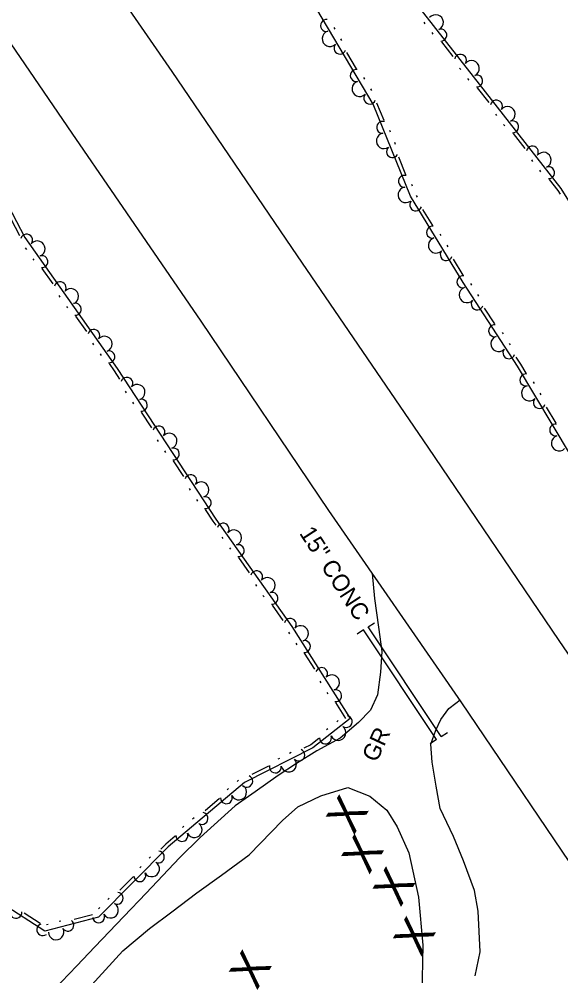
# Model space of a CAD drawing. Extents: x 2030130 to 2036320, y 723205 to 762423.
# Drawn here: x 2034186.4 to 2034304.6, y 759843.4 to 760052.2 of the extents above; entities that cross this region are included whole.
import ezdxf

# ---------------------------------------------------------------- set-up
doc = ezdxf.new("R2010")
doc.units = 0
for name, color, linetype in [('Draft_Station Labels Major', 7, 'Continuous'), ('Draft_Station Tics Major', 7, 'Continuous'), ('Draft_Station Tics Minor', 7, 'Continuous'), ('Old_Level_23', 7, 'Continuous'), ('Old_Level_26', 7, 'Continuous')]:
    doc.layers.add(name, color=color, linetype=linetype)

msp = doc.modelspace()

# ---------------------------------------------------------------- linework, layer by layer
at = {"layer": 'Draft_Station Labels Major'}
for points in [[(2033718.38, 760730.67), (2033746.51, 760689.6), (2033774.62, 760648.49), (2033802.7, 760607.26), (2033830.67, 760566.06), (2033858.89, 760525.01), (2033886.8, 760483.79), (2033914.88, 760442.66), (2033945.45, 760397.69), (2033973.64, 760356.6), (2034001.68, 760315.42), (2034029.6, 760274.28), (2034057.68, 760233.24), (2034085.75, 760192.04), (2034113.77, 760150.87), (2034141.95, 760109.94), (2034159.83, 760083.11), (2034175.33, 760060.45), (2034197.95, 760027.35), (2034226.1, 759986.31), (2034253.95, 759945.01), (2034282.77, 759903.21), (2034311.52, 759860.74)], [(2034332.4, 759875.51), (2034304.28, 759916.6), (2034275.65, 759958.8), (2034247.14, 760000.6), (2034219.84, 760040.78), (2034191.61, 760081.68), (2034163.74, 760123.03), (2034135.88, 760163.98), (2034107.11, 760206.11), (2034080.34, 760245.23), (2034051.49, 760287.62), (2034022.91, 760329.48), (2033995.09, 760369.99), (2033966.89, 760411.11), (2033935.74, 760457.29), (2033907.97, 760498.26), (2033880.46, 760539.38), (2033851.33, 760582.23)], [(2034263.43, 759931.23), (2034263.96, 759925.76), (2034264.85, 759919.56), (2034265.6, 759914.2), (2034265.3, 759909.74), (2034264.64, 759904.78), (2034263.09, 759901.44), (2034260.51, 759898.71), (2034256.46, 759895.31), (2034251.41, 759892.53), (2034246.96, 759889.75), (2034242.98, 759887.18), (2034237.9, 759883.6), (2034233.6, 759880.5), (2034225.96, 759873.65), (2034221.39, 759869.16), (2034214.15, 759861.5), (2034209.26, 759856.38), (2034202.93, 759849.74), (2034199.01, 759845.6), (2034193.99, 759840.41)], [(2034285.94, 759843.41), (2034287.05, 759848.7), (2034286.58, 759857.57), (2034285.78, 759862.06), (2034283.38, 759868.54), (2034281.18, 759873.85), (2034278.31, 759879.94), (2034277.4, 759884.81), (2034276.56, 759890.09), (2034276.23, 759893.99), (2034277.35, 759897.08), (2034278.42, 759899.37), (2034280.2, 759901.79), (2034281.69, 759902.96), (2034282.66, 759903.64)], [(2034201.48, 759840.6), (2034209.03, 759848.89), (2034214.9, 759853.77), (2034219.75, 759857.37), (2034225.21, 759861.55), (2034230.58, 759865.43), (2034236.63, 759869.86), (2034243.9, 759877.35), (2034247.25, 759880.33), (2034252.29, 759882.71), (2034258.18, 759884.52), (2034262.96, 759882.65), (2034266.63, 759879.62), (2034268.94, 759875.92), (2034271.46, 759870.27), (2034273.55, 759860.57), (2034274.52, 759850.16), (2034274.27, 759839.19)]]:
    msp.add_lwpolyline(points, dxfattribs=at)
msp.add_spline([(2034040.65, 759871.53), (2034053.57, 759856.73), (2034085.12, 759821.41), (2034121.23, 759781.88), (2034160.8, 759738.89), (2034194.89, 759702.59)], degree=3, dxfattribs=at)
at = {"layer": 'Draft_Station Tics Major'}
for points in [[(2033865.22, 760655.09), (2033891.74, 760610.39), (2033928.27, 760560.61), (2033957.26, 760512.4), (2033990.84, 760466.46), (2034027.29, 760415.57), (2034062.79, 760367.8), (2034100.45, 760308.07), (2034126.3, 760269.13), (2034147.67, 760241.66), (2034171.15, 760213.5), (2034188.43, 760192.75), (2034201.98, 760164.61), (2034214.77, 760146.29), (2034228.35, 760126.12), (2034239.08, 760107.39), (2034248.43, 760090.51), (2034260.06, 760075.4), (2034270.93, 760058.37), (2034285.47, 760039.75), (2034304.65, 760015.27), (2034321.95, 759987.59), (2034348.43, 759946.8)], [(2034326.75, 759923.45), (2034306.73, 759957.16), (2034295.18, 759976.5), (2034283.32, 759994.79), (2034271.8, 760013.59), (2034263.7, 760033.69), (2034251.35, 760054.43), (2034226.75, 760080.43), (2034216.04, 760102), (2034205.31, 760120.49), (2034188.73, 760144.18), (2034176.71, 760159.19)], [(2034255.38, 760050.07), (2034255.17, 760050.42)], [(2034274.7, 760051.55), (2034274.95, 760051.23)], [(2034276.46, 760049.29), (2034276.71, 760048.97)], [(2034256.84, 760047.6), (2034256.63, 760047.96)], [(2034278.55, 760047.28), (2034281.07, 760044.05)], [(2034260.06, 760041.4), (2034257.96, 760044.93)], [(2034282.52, 760041.53), (2034282.77, 760041.21)], [(2034261.88, 760039.15), (2034261.67, 760039.5)], [(2034284.28, 760039.27), (2034284.5, 760038.99), (2034284.53, 760038.95)], [(2034263.35, 760036.68), (2034263.14, 760037.03)], [(2034286.38, 760037.26), (2034288.91, 760034.03)], [(2034266.04, 760030.08), (2034264.51, 760033.88)], [(2034290.35, 760031.52), (2034290.61, 760031.2)], [(2034173.85, 760031), (2034187.64, 760004.61), (2034207.84, 759975.95), (2034229.38, 759943.13), (2034245.9, 759919.69), (2034258.64, 759899.6), (2034250.52, 759893.18), (2034235.61, 759885.65), (2034218.97, 759871.56), (2034203.75, 759856.25), (2034192.07, 759853.18), (2034182.82, 759859.15)], [(2034292.12, 760029.26), (2034292.38, 760028.94)], [(2034267.49, 760027.57), (2034267.34, 760027.95)], [(2034294.22, 760027.25), (2034296.75, 760024.02)], [(2034268.56, 760024.91), (2034268.41, 760025.29)], [(2034270.79, 760018.29), (2034269.26, 760022.09)], [(2034298.2, 760021.51), (2034298.45, 760021.19)], [(2034299.97, 760019.25), (2034300.22, 760018.93)], [(2034302.06, 760017.24), (2034303.98, 760014.8), (2034304.46, 760014.03)], [(2034272.24, 760015.78), (2034272.09, 760016.16)], [(2034273.37, 760013.37), (2034273.16, 760013.72)], [(2034276.67, 760007.21), (2034274.52, 760010.71)], [(2034184.6, 760008.66), (2034186.5, 760005.02)], [(2034278.52, 760004.98), (2034278.3, 760005.33)], [(2034187.77, 760002.29), (2034188.01, 760001.95)], [(2034280.02, 760002.53), (2034279.8, 760002.88)], [(2034189.43, 759999.94), (2034189.66, 759999.6)], [(2034283.31, 759996.37), (2034281.17, 759999.87)], [(2034191.41, 759997.83), (2034193.78, 759994.48)], [(2034285.18, 759994.19), (2034284.95, 759994.53)], [(2034195.1, 759991.89), (2034195.33, 759991.56)], [(2034286.74, 759991.78), (2034286.51, 759992.12)], [(2034196.75, 759989.55), (2034196.99, 759989.21)], [(2034198.74, 759987.44), (2034201.1, 759984.09)], [(2034290.19, 759985.71), (2034287.96, 759989.15)], [(2034292.09, 759983.53), (2034291.87, 759983.87)], [(2034202.42, 759981.5), (2034202.66, 759981.17)], [(2034293.66, 759981.12), (2034293.43, 759981.46)], [(2034204.08, 759979.16), (2034204.31, 759978.82)], [(2034206.07, 759977.05), (2034207.16, 759975.49), (2034208.35, 759973.68)], [(2034297.05, 759974.97), (2034295.88, 759976.94), (2034294.88, 759978.49)], [(2034298.88, 759972.72), (2034298.67, 759973.07)], [(2034209.58, 759971.05), (2034209.81, 759970.71)], [(2034211.16, 759968.65), (2034211.39, 759968.31)], [(2034300.35, 759970.25), (2034300.14, 759970.61)], [(2034303.57, 759964.06), (2034301.47, 759967.58)], [(2034213.08, 759966.48), (2034215.33, 759963.05)], [(2034216.56, 759960.43), (2034216.79, 759960.08)], [(2034218.14, 759958.02), (2034218.36, 759957.68)], [(2034220.06, 759955.85), (2034222.31, 759952.42)], [(2034223.54, 759949.8), (2034223.76, 759949.45)], [(2034225.11, 759947.4), (2034225.34, 759947.05)], [(2034227.03, 759945.22), (2034228.71, 759942.67), (2034229.33, 759941.79)], [(2034230.65, 759939.21), (2034230.88, 759938.87)], [(2034232.3, 759936.86), (2034232.53, 759936.53)], [(2034234.29, 759934.75), (2034236.65, 759931.4)], [(2034237.97, 759928.81), (2034238.2, 759928.48)], [(2034239.62, 759926.47), (2034239.86, 759926.13)], [(2034241.61, 759924.36), (2034243.97, 759921)], [(2034245.23, 759918.45), (2034245.45, 759918.11)], [(2034246.77, 759916.03), (2034246.99, 759915.68)], [(2034248.65, 759913.82), (2034250.85, 759910.36)], [(2034252.04, 759907.72), (2034252.26, 759907.37)], [(2034253.57, 759905.29), (2034253.79, 759904.95)], [(2034255.46, 759903.09), (2034257.66, 759899.62)], [(2034256.06, 759899.13), (2034255.74, 759898.87)], [(2034253.81, 759897.35), (2034253.49, 759897.09)], [(2034251.81, 759895.24), (2034250.07, 759893.87), (2034248.54, 759893.09)], [(2034245.79, 759892.17), (2034245.42, 759891.98)], [(2034243.23, 759890.87), (2034242.86, 759890.69)], [(2034240.85, 759889.21), (2034237.19, 759887.36)], [(2034234.29, 759886.14), (2034233.98, 759885.87)], [(2034232.1, 759884.29), (2034231.79, 759884.02)], [(2034230.17, 759882.12), (2034227.04, 759879.47)], [(2034224.59, 759877.93), (2034224.27, 759877.66)], [(2034222.4, 759876.07), (2034222.08, 759875.81)], [(2034220.47, 759873.9), (2034218.41, 759872.16), (2034217.37, 759871.11)], [(2034215.06, 759869.37), (2034214.77, 759869.08)], [(2034213.03, 759867.33), (2034212.74, 759867.04)], [(2034211.3, 759865.01), (2034208.41, 759862.1)], [(2034206.1, 759860.35), (2034205.81, 759860.06)], [(2034204.07, 759858.32), (2034203.78, 759858.03)], [(2034190.99, 759854.85), (2034187.54, 759857.08)], [(2034202.4, 759856.74), (2034198.43, 759855.7)], [(2034192.78, 759854.64), (2034192.38, 759854.54)], [(2034195.55, 759855.37), (2034195.16, 759855.27)]]:
    msp.add_lwpolyline(points, dxfattribs=at)
for centre, radius, start, end in [((2034277.32, 760051.52), 1.69, 293.9308, 142.0033), ((2034253.48, 760050.85), 1.3, 81.5456, 282.3422), ((2034254.24, 760047.96), 1.69, 106.7409, 314.8133), ((2034278.44, 760048.75), 1.3, 268.7356, 109.5321), ((2034256.42, 760045.92), 1.3, 139.2121, 340.0086), ((2034282.73, 760043.26), 1.3, 326.402, 167.1986), ((2034285.14, 760041.5), 1.69, 293.9308, 142.0033), ((2034259.98, 760039.93), 1.3, 81.5456, 282.3422), ((2034286.26, 760038.73), 1.3, 268.8534, 109.65), ((2034260.75, 760037.04), 1.69, 106.7409, 314.8133), ((2034262.92, 760034.99), 1.3, 139.2121, 340.0086), ((2034290.56, 760033.24), 1.3, 326.5199, 167.3164), ((2034292.98, 760031.49), 1.69, 294.0487, 142.1212), ((2034265.74, 760028.63), 1.3, 72.7157, 273.5122), ((2034294.11, 760028.73), 1.3, 268.8534, 109.65), ((2034266.05, 760025.66), 1.69, 97.9109, 305.9834), ((2034267.88, 760023.31), 1.3, 130.3821, 331.1787), ((2034298.41, 760023.24), 1.3, 326.5199, 167.3164), ((2034300.82, 760021.48), 1.69, 294.0487, 142.1212), ((2034301.95, 760018.72), 1.3, 268.8534, 109.65), ((2034270.49, 760016.84), 1.3, 72.7157, 273.5122), ((2034270.8, 760013.87), 1.69, 97.9109, 305.9834), ((2034272.97, 760011.68), 1.3, 139.9358, 340.7323), ((2034276.61, 760005.74), 1.3, 82.2693, 283.0659), ((2034188.07, 760004), 1.3, 323.6174, 164.4139), ((2034277.41, 760002.86), 1.69, 107.4646, 315.5371), ((2034190.39, 760002.13), 1.69, 291.1462, 139.2187), ((2034191.38, 759999.31), 1.3, 265.9509, 106.7475), ((2034279.61, 760000.84), 1.3, 139.9358, 340.7323), ((2034283.25, 759994.9), 1.3, 82.2693, 283.0659), ((2034195.39, 759993.61), 1.3, 323.6174, 164.4139), ((2034197.72, 759991.73), 1.69, 291.1462, 139.2187), ((2034284.12, 759992.04), 1.69, 108.9411, 317.0136), ((2034198.7, 759988.92), 1.3, 265.9509, 106.7475), ((2034286.37, 759990.08), 1.3, 141.4123, 342.2088), ((2034290.17, 759984.23), 1.3, 83.7458, 284.5424), ((2034202.72, 759983.22), 1.3, 323.6174, 164.4139), ((2034205.04, 759981.34), 1.69, 291.1462, 139.2187), ((2034291.04, 759981.38), 1.69, 108.9411, 317.0136), ((2034206.03, 759978.53), 1.3, 265.9509, 106.7475), ((2034293.29, 759979.41), 1.3, 141.4123, 342.2088), ((2034209.94, 759972.76), 1.3, 321.7177, 162.5142), ((2034296.98, 759973.5), 1.3, 81.5934, 282.39), ((2034212.2, 759970.81), 1.69, 289.2465, 137.319), ((2034297.74, 759970.61), 1.69, 106.7887, 314.8612), ((2034213.09, 759967.96), 1.3, 264.0512, 104.8478), ((2034299.92, 759968.57), 1.3, 139.2599, 340.0564), ((2034216.92, 759962.13), 1.3, 321.7177, 162.5142), ((2034303.49, 759962.58), 1.3, 81.5934, 282.39), ((2034219.18, 759960.18), 1.69, 289.2465, 137.319), ((2034304.26, 759959.69), 1.69, 106.7887, 314.8612), ((2034220.07, 759957.33), 1.3, 264.0512, 104.8478), ((2034223.89, 759951.5), 1.3, 321.7177, 162.5142), ((2034226.15, 759949.55), 1.69, 289.2465, 137.319), ((2034227.04, 759946.7), 1.3, 264.0512, 104.8478), ((2034230.94, 759940.92), 1.3, 323.5986, 164.3952), ((2034233.27, 759939.05), 1.69, 291.1274, 139.1999), ((2034234.25, 759936.23), 1.3, 265.9321, 106.7287), ((2034238.26, 759930.53), 1.3, 323.5986, 164.3952), ((2034240.59, 759928.65), 1.69, 291.1274, 139.1999), ((2034241.57, 759925.83), 1.3, 265.9321, 106.7287), ((2034245.59, 759920.14), 1.3, 323.5986, 164.3952), ((2034247.84, 759918.17), 1.69, 288.3518, 136.4243), ((2034248.68, 759915.3), 1.3, 263.1565, 103.9531), ((2034252.42, 759909.41), 1.3, 320.823, 161.6196), ((2034254.65, 759907.43), 1.69, 288.3518, 136.4243), ((2034255.49, 759904.57), 1.3, 263.1565, 103.9531), ((2034257.79, 759898.92), 1.3, 236.7568, 77.5534), ((2034256.04, 759896.5), 1.69, 204.2856, 52.3581), ((2034253.28, 759895.36), 1.3, 179.0903, 19.8869), ((2034247.44, 759891.62), 1.3, 225.2341, 66.0307), ((2034242.32, 759889.03), 1.3, 167.5677, 8.3642), ((2034245.25, 759889.6), 1.69, 192.7629, 40.8354), ((2034236.09, 759885.89), 1.3, 225.2341, 66.0307), ((2034234.36, 759883.52), 1.69, 206.2149, 54.2874), ((2034231.64, 759882.29), 1.3, 181.0196, 21.8162), ((2034226.32, 759877.78), 1.3, 238.6861, 79.4827), ((2034224.66, 759875.3), 1.69, 206.2149, 54.2874), ((2034221.94, 759874.07), 1.3, 181.0196, 21.8162), ((2034216.8, 759869.37), 1.3, 243.5997, 84.3963), ((2034215.36, 759866.76), 1.69, 211.1285, 59.201), ((2034212.75, 759865.3), 1.3, 185.9332, 26.7298), ((2034207.83, 759860.36), 1.3, 243.5997, 84.3963), ((2034206.39, 759857.74), 1.69, 211.1285, 59.201), ((2034185.72, 759857.28), 1.3, 165.5645, 6.3611), ((2034203.79, 759856.29), 1.3, 185.9332, 26.7298), ((2034191.58, 759853.5), 1.3, 107.898, 308.6946), ((2034194.49, 759852.97), 1.69, 180.6877, 28.7602), ((2034197.06, 759854.49), 1.3, 213.1589, 53.9555)]:
    msp.add_arc(centre, radius, start, end, dxfattribs=at)
at = {"layer": 'Draft_Station Tics Minor'}
for p, q in [((2034261.58, 759918.92), (2034260.21, 759918.01)), ((2034262.61, 759919.6), (2034263.97, 759920.51)), ((2034278.49, 759895.66), (2034279.86, 759896.57)), ((2034277.47, 759894.98), (2034276.1, 759894.07))]:
    msp.add_line(p, q, dxfattribs=at)
for points in [[(2034277.47, 759894.98), (2034261.58, 759918.92)], [(2034278.49, 759895.66), (2034262.61, 759919.6)]]:
    msp.add_lwpolyline(points, dxfattribs=at)

# ---------------------------------------------------------------- texts
at = {"layer": 'Draft_Station Tics Major'}
for p in [(2034259.42, 759873.99), (2034262.77, 759865.38), (2034269.62, 759858.26), (2034274.07, 759847.45), (2034238.28, 759840.13)]:
    msp.add_text('X', height=7.38, rotation=58.9267, dxfattribs=at).set_placement(p)
at = {"layer": 'Old_Level_23'}
msp.add_text('GR', height=3.691, rotation=65, dxfattribs=at).set_placement((2034264.42, 759889.84))
at = {"layer": 'Old_Level_26'}
msp.add_text('15" CONC', height=3.691, rotation=303.0133, dxfattribs=at).set_placement((2034247.45, 759940.04))

doc.saveas('drawing.dxf')
